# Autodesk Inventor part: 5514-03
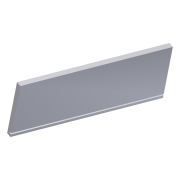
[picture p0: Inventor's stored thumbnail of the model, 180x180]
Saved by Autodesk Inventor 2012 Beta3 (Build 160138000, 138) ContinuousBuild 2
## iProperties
Created: 2011-02
Part Number: 5514-03
Material: Default
Document SubType Name: Modeling
Designer: Beta-8540w
Density: 1 g/cm^3
Author: Beta-8540w
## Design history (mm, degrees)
derived "c15-12.ipt" dims "d2" = 12.7, "d3" = 0, "d4" = 6.35, "d6" = 6.35, "d7" = 0, "width" = 342.9, "height" = 127, "thickness" = 3.302
body "Solid1"
feature "Solid1::c15-12.ipt" dims "d2" = 12.7, "d3" = 0, "d4" = 6.35, "d6" = 6.35, "d7" = 0, "width" = 342.9, "height" = 127, "thickness" = 3.302, "ScaleForDerivedMember" = 10
tag "TaggingFeature1"
